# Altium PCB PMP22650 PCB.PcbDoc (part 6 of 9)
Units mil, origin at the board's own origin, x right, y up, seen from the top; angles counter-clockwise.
Board outline 11311 x 5233 mil, 8 copper layers (Layer 1, Layer 2, Layer 3, Layer 4, Layer 5, Layer 6, Layer 7, Layer 8), stack 88.6 mil thick; 633 components, 410 nets, 2503 pads, 1993 vias.
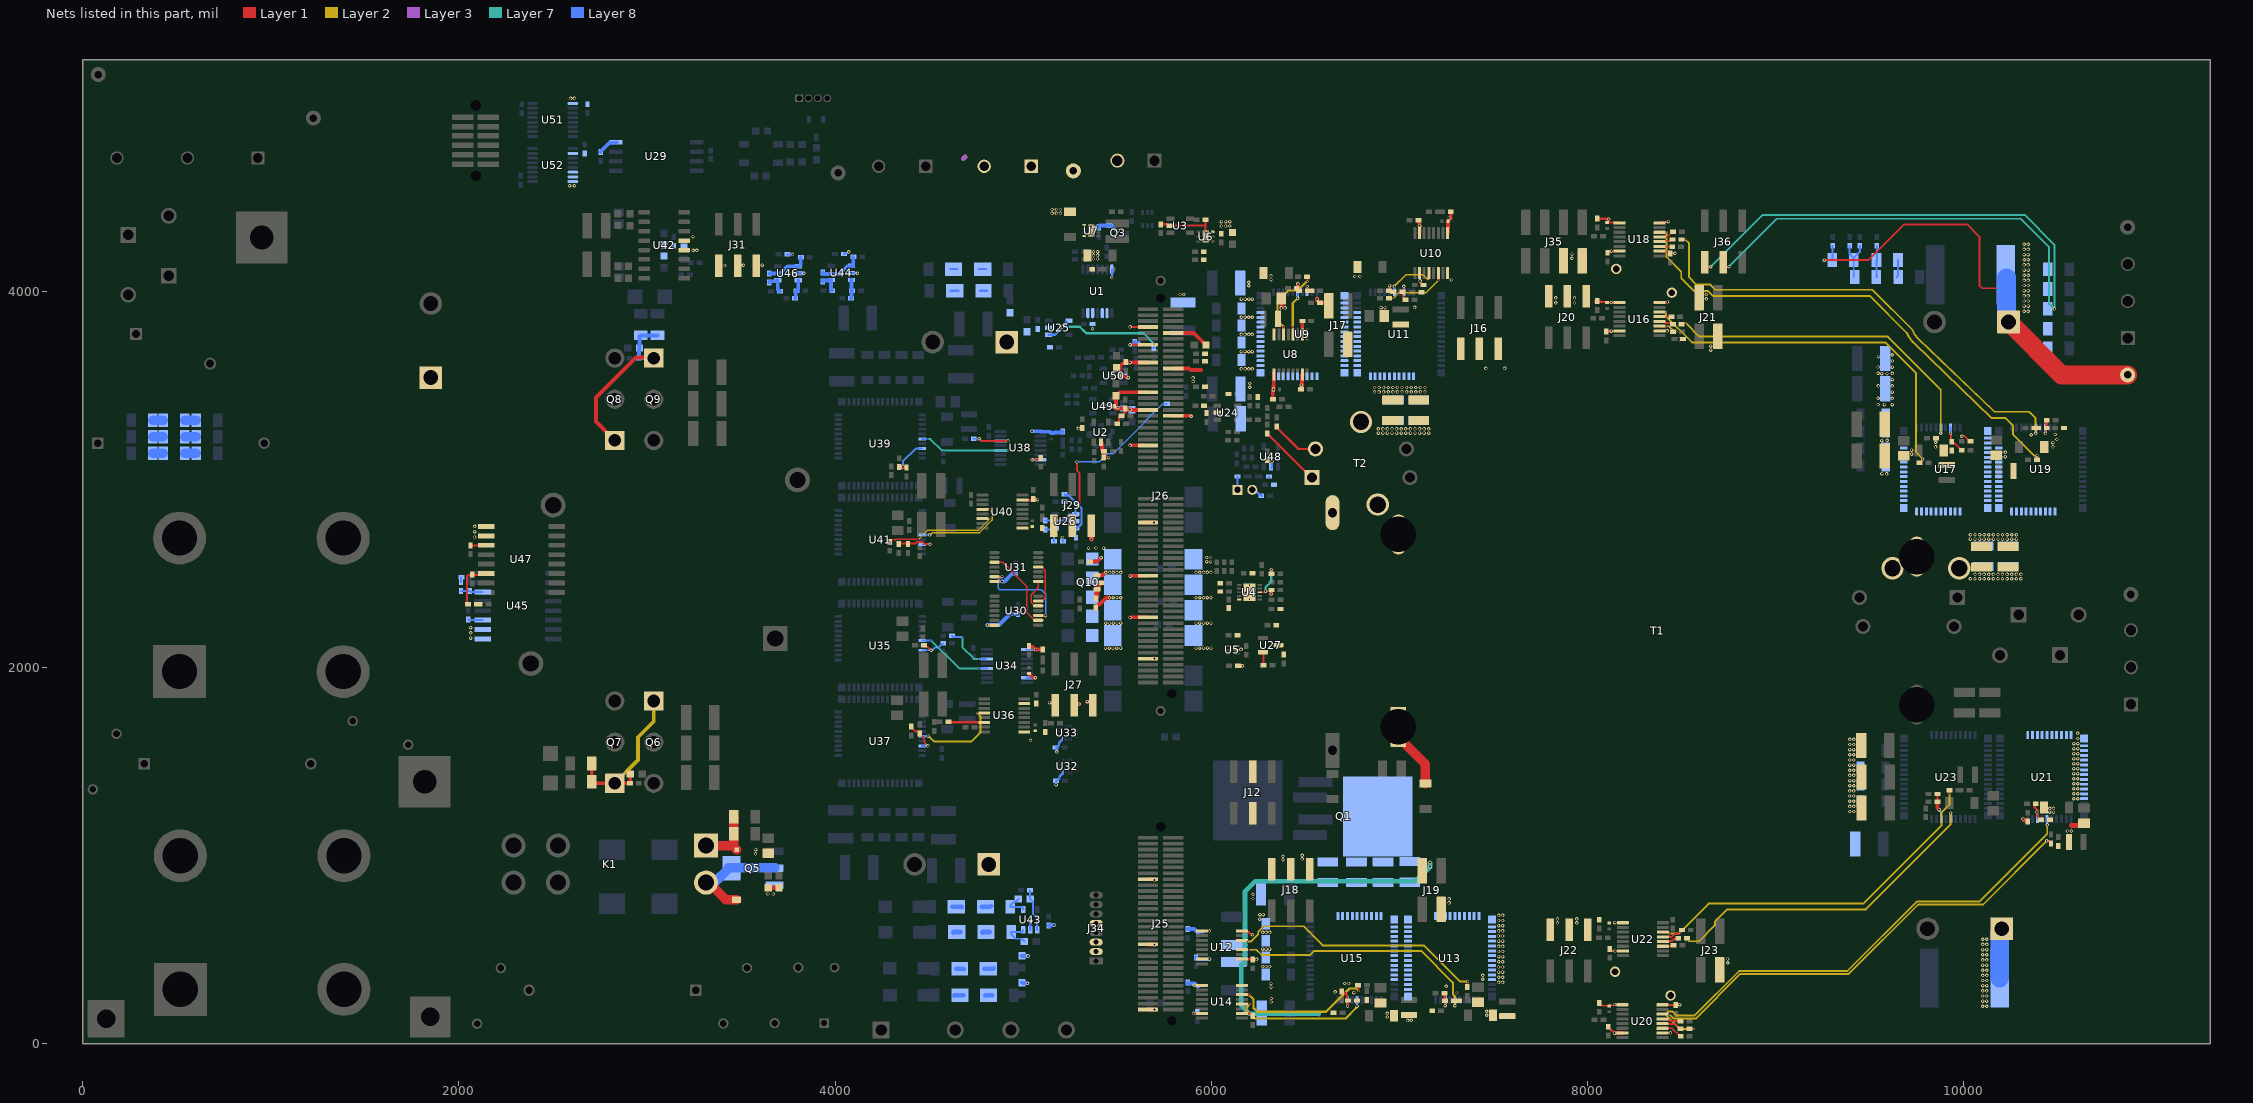
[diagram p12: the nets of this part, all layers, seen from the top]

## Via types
v1: diameter 18, hole 10, Layer 1 to Layer 8, 1759 vias
v2: diameter 8, hole 4, Layer 1 to Layer 2, 160 vias
v3: diameter 18, hole 10, Layer 1 to Layer 8, tented both sides, 34 vias
v4: diameter 8, hole 4, Layer 7 to Layer 8, 28 vias
v5: diameter 19.68, hole 7.87, Layer 1 to Layer 8, 8 vias
v6: diameter 118.11, hole 86.61, Layer 1 to Layer 8, 4 vias

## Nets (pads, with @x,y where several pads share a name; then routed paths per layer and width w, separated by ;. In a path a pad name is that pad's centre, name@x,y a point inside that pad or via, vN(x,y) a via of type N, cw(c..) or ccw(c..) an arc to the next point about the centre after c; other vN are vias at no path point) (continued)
NetR29_1: R29.1 U8.6 | length 409.5
  Layer 1 w10: R29.1@6508.62,4078 6511.62,4075 v2@6511.62,4054.62
  Layer 1 w12: U8.6@6382.27,3778.6 6383.63,3779.96 6383.63,3814.22 v2(6383.29,3814.57)
  Layer 2 w12: v2@6382,3816 6351.65,3846.35 6351.65,3948.65 6409,4006 6459.01,4006 6507.01,4054 v2@6511,4054
  other v2: 6511.62,4054
NetR34_1: R34.1 U10.6 | length 351.2
  Layer 1 w10: R34.1@6935,3963 6937,3965 R34.1@6944.62,3965 v2(6967,3965) ; U10.6@7207,4098 7207.69,4097.31 v2(7207.69,4059.9)
  Layer 2 w8: v2(6967,3965) 6968,3965 6998,3995 7142.8,3995 v2(7207.69,4059.9)
NetR39_1: R39.1 U12.6 | length 1396.3
  Layer 1 w10: U12.6@6162.57,551.05 6185.99,551.05 U12.6@6192.42,544.62 ; v1(7361,332) 7361,307 R39.1@7363,305 ; R39.1@7363,302 R39.1@7363,305 ; R39.1@7364,304 R39.1@7363,305
  Layer 2 w10: v2(6192.44,544.69) 6210.27,544.69 6249,583.42 6249,596.22 6253.82,601.05 6278.78,626 6490,626 6591.5,524.5 7130.26,524.5 7322.76,332 v1(7361,332)
NetR44_1: R44.1 U14.6 | length 777
  Layer 1 w12: U14.6@6162.57,262.05 U14.6@6164.07,260.55 ; U14.6@6163.27,262.6 6163.82,262.05 v2@6202.57,262.05 ; R44.1@6778.88,313.5 R44.1@6779.38,313 ; R44.1@6781,314 6782,313 v2(6782,283)
  Layer 2 w12: v2(6202,262) 6202,259.53 6209.03,252.5 6209.83,252.5 6224,238.33 6224,191 6244,171 6610,171 6734,295 6770,295 v2(6782,283)
NetR49_1: R49.1 U16.6 | length 2008.2
  Layer 1 w10: U16.6@8391,3891 8392,3892 v2(8418,3892) ; R49.1@9764,3089 R49.1@9765.38,3089 9769.32,3089 9776.13,3095.81 9776.13,3101.13 9780.47,3105.47 9780.47,3108.47 v1(9782,3110)
  Layer 2 w10: v2@8417,3892 8417,3868 8555.4,3729.6 9582.8,3729.6 9746.5,3565.91 9746.5,3145.5 v1(9782,3110)
NetR54_1: R54.1 U18.6 | length 2648.3
  Layer 1 w10: U18.6@8385,4315 8386,4316 v2(8420,4316) ; R54.1@10388,3106 10389,3107 v1(10389,3128)
  Layer 2 w10: v2(8420,4316) 8420,4184 8498.3,4105.7 8498.3,4071.11 8565.31,4004.1 8639.34,4004.1 8666.44,3977 9501,3977 9698.03,3779.97 9698.03,3777.87 9709.36,3758.68 ccw(c9844.57,3838.57) 9735.86,3725.23 10150,3328 10222.58,3328 10225.51,3325.07 10261,3289.58 10261,3240.42 10374.24,3127.18 v1@10389.82,3127.18
NetR59_1: R59.1 U20.6 | length 2471.6
  Layer 1 w10: U20.6@8405,160 8407,158 v2(8435,158) ; v1@10442.81,1081.61 v1(10441.28,1080.08) 10442.81,1078.55 10453.45,1078.55 10455.87,1076.13 10457.19,1076.13 10466,1067.32 R59.1@10466,1066
  Layer 2 w10: v2(8435,158) 8458,135 8575,135 8812.5,372.5 9388.31,372.5 9757.31,741.5 10102.69,741.5 v1(10441.28,1080.08)
NetR64_1: R64.1 U22.6 | length 1927.4
  Layer 1 w10: U22.6@8399,594 8401.57,591.43 8433.54,591.43 v2(8438,587) ; v2(9925,1332) 9925,1346 R64.1@9926,1347
  Layer 2 w10: v2(8438,587) 8484,587 8643.5,746.5 9466.74,746.5 9882.29,1162.05 9882.29,1231.71 9890.21,1239.63 9890.21,1240.21 9925,1275 v2(9925,1332)
NetR74_1: R74.1 U25.1 U25.4 | length 712
  Layer 7 w12: v1(5208.27,3812.6) 5300.43,3812.6 5328,3785.03 5335.03,3778 5640,3778 v4(5696,3722)
  Layer 8 w12: U25.1@5134.79,3771.2 5168.25,3771.2 5229.37,3832.31 5229.37,3840.19 5208.27,3819.09 v1(5208.27,3812.6) ; R74.1@5693,3699.62 5696,3702.62 v4@5696,3721
NetR75_1: R75.1 R76.2 | length 41.6
  Layer 8 w12: R76.2@4763.35,4119.6 R75.1@4804.98,4119.6
NetR76_1: R76.1 R77.2 | length 38.8
  Layer 8 w12: R77.2@4610.35,4119.6 R76.1@4649.18,4119.6
NetR78_2: R78.2 R83.1 U26.4 | length 121.7
  Layer 8 w12: R83.1@5116.05,2735.44 5154.82,2735.44 U26.4@5162.05,2742.67 ; R78.2@5163.43,2673.07 5163.43,2736.85 5169.24,2742.67 U26.4@5169.92,2742.67
NetR79_2: R79.2 R82.2 U26.3 | length 290.1
  Layer 8 w12: R79.2@5219.5,2922.58 5225.31,2916.76 5240.24,2916.76 5309.37,2847.63 5309.37,2764.67 5301.46,2756.76 5300.15,2756.76 5286.06,2742.67 U26.3@5278.19,2742.67 R82.2@5278.19,2696.69
NetR80_1: R80.1 R83.2 U26.1 | length 1077.9
  Layer 1 w10: v1(5278,2849) 5299.76,2870.76 5299.76,3035.49 5284.88,3050.37 v1(5284.88,3094.25)
  Layer 8 w8: v1(5284.88,3094.25) 5403.76,3094.25 5434.77,3125.26 5446.51,3137 5477.67,3137 5647.77,3307.1 5647.77,3310.88 5737.04,3400.15 5760.18,3400.15 R80.1@5763.89,3403.86
  Layer 8 w10: v1(5278,2849) 5278,2817.87 U26.1@5278.27,2817.6
  Layer 8 w12: R83.2@5116.05,2782.69 5213.69,2782.69 5244.94,2813.94 5274.66,2813.94 U26.1@5278.19,2817.47
NetR81_1: R81.1 U27.2 | length 69.7
  Layer 1 w12: U27.2@6274.4,2082.92 6277.12,2080.2 R81.1@6277.12,2014.32
NetR94_1: R94.1 R95.2 | length 35.7
  Layer 8 w12: R95.2@4770.47,4004.6 R94.1@4806.18,4004.6
NetR95_1: R95.1 R96.2 | length 41.9
  Layer 8 w12: R96.2@4614.35,4004.6 R95.1@4656.3,4004.6
NetR100_1: R100.1 U34.6 | length 265.6
  Layer 7 w10: v4(4676.65,2164.26) 4676.65,2109.22 4738.38,2047.48 v4@4763.15,2047.48
  Layer 8 w10: R100.1@4621.89,2169.7 4627.33,2164.26 v4(4676.65,2164.26) ; v4(4761.97,2047.1) 4802.77,2047.1 U34.6@4803.27,2047.6
NetR105_1: R105.1 U36.6 | length 192.3
  Layer 1 w12: R105.1@4601,1711 4601.25,1710.75 4791.45,1710.75 U36.6@4792.7,1709.5
NetR110_1: R110.1 U38.6 | length 231.5
  Layer 1 w10: v1(4765,3218) 4776.9,3206.1 v1(4918.97,3206.1)
  Layer 8 w8: U38.6@4878.27,3207.6 4879.77,3206.1 v1(4918.97,3206.1)
  Layer 8 w10: R110.1@4734.27,3216.6 4735.67,3218 v1(4765,3218)
NetR115_1: R115.1 U40.6 | length 625.3
  Layer 1 w8: R115.1@4289,2673 4297.37,2681.37 4320.79,2681.37 4322.42,2683 v2(4444,2683) ; U40.6@4778,2792 v2(4820,2792)
  Layer 2 w8: v2@4442.67,2682.67 4490.6,2730.6 4519.52,2730.6 4521.42,2732.5 4762.5,2732.5 4821,2791 v2@4821,2792
NetR125_2: R125.2 R129.2 U43.3 | length 167.3
  Layer 8 w10: U43.3@4999.22,606.46 4999.22,601.61 4992.4,594.8 R129.2@4935.71,594.8 4935.71,583.98 4960.39,559.3 4991.42,559.3 R125.2@5005.12,545.6
NetR126_2: R126.2 R131.2 U44.3 | length 100.5
  Layer 8 w20: R126.2@4084.82,3964.55 4085.19,3964.55 4087.01,3966.36 4087.01,4003.14 R131.2@4088.82,4004.95 ; U44.3@4086.62,4061.63 4086.62,4006.76 4088.43,4004.95 R131.2@4088.82,4004.95 ; R131.2@4089.19,4004.95 R131.2@4088.82,4004.95
NetR127_2: R127.2 R128.1 | length 40.2
  Layer 8 w25: R127.2@4628.27,592.6 4630.47,594.8 R128.1@4667.54,594.8
NetR128_2: R128.2 R129.1 | length 39.2
  Layer 8 w25: R128.2@4783.27,592.6 4785.47,594.8 R129.1@4821.54,594.8
NetR130_1: R130.1 R139.2 U43.1 | length 226.7
  Layer 8 w10: R130.1@5035.24,816.6 5035.24,772.47 R139.2@5037.11,770.6 5038.01,770.6 5051.71,756.9 5051.71,691.87 5074.02,669.56 U43.1@5074.02,606.46
NetR132_2: R132.2 R138.1 U45.14 | length 117.5
  Layer 8 w10: R132.2@2010.65,2408.25 R138.1@2057.89,2408.25 2062.54,2403.6 U45.14@2126.26,2403.6
NetR133_1: R133.1 R140.2 U44.1 | length 232.7
  Layer 8 w20: R140.2@3933.69,4101.17 3933.69,4097.23 3935.51,4095.42 3939.44,4095.42 3940.99,4093.87 4023.14,4093.87 4063.89,4134.62 4084.8,4134.62 U44.1@4086.62,4136.43 4094.49,4136.43 4096.57,4138.51 R133.1@4096.57,4184.55
NetR134_2: R134.2 R135.1 | length 50.1
  Layer 8 w25: R134.2@4623.71,728.8 R135.1@4664.54,728.8 4672.06,728.8 R135.1@4673.27,727.6
NetR135_2: R135.2 R136.1 | length 51.1
  Layer 8 w25: R135.2@4778.71,728.8 R136.1@4817.54,728.8 4824.47,728.8 R136.1@4828.27,732.6
NetR136_2: R136.2 R139.1 U43.4 | length 141.7
  Layer 8 w10: R139.1@4974.12,770.6 4960.42,756.9 4952.3,756.9 4931.71,736.31 R136.2@4931.71,728.8 4992.4,728.8 4999.22,721.99 U43.4@4999.22,714.73
NetR137_2: R137.2 R140.1 U44.4 | length 111.6
  Layer 8 w20: R140.1@3933.69,4053.93 3933.69,4057.86 3935.51,4059.67 3968.52,4059.67 3970.47,4061.63 U44.4@3978.35,4061.63 3978.35,4006.98 3980.38,4004.95 R137.2@3984.32,4004.95
NetR142_1: R142.1 R143.2 | length 50.1
  Layer 8 w25: R142.1@4633.27,257.6 4635.27,259.6 R142.1@4643.7,259.6 R143.2@4682.53,259.6
NetR143_1: R143.1 R144.2 | length 38.1
  Layer 8 w25: R143.1@4798.27,257.6 4799.77,259.1 4835.03,259.1 R144.2@4835.53,258.6
NetR145_1: R145.1 R146.2 U46.3 | length 104.9
  Layer 8 w20: R145.1@3787.51,3965.57 3788.77,3965.57 3790.58,3967.38 3790.58,4001.75 3792.39,4003.57 R146.2@3793.65,4003.57 3797.58,4003.57 3803.31,4009.29 U46.3@3803.31,4060.16
NetR148_1: R148.1 R154.2 U46.1 | length 226.5
  Layer 8 w20: R154.2@3649.89,4096.19 3708.5,4096.19 3747.28,4134.97 U46.1@3803.31,4134.97 3811.18,4134.97 3817.27,4141.05 R148.1@3817.27,4181.57
NetR149_2: R149.2 R155.1 U47.14 | length 242.5
  Layer 1 w10: R149.2@2047,2338 2043,2342 2043,2487.61 2048.86,2493.47 2123.13,2493.47 U47.14@2129.26,2499.6
NetR150_1: R150.1 R151.2 | length 40.8
  Layer 8 w25: R150.1@4643.7,400.6 R151.2@4679.53,400.6 4680.27,400.6 R151.2@4683.27,397.6
NetR151_1: R151.1 R152.2 | length 50.4
  Layer 8 w25: R151.1@4793.7,400.6 R152.2@4835.53,400.6 4841.27,400.6 R152.2@4843.27,402.6
NetR153_2: R153.2 R154.1 U46.4 | length 116.8
  Layer 8 w20: R154.1@3649.89,4048.94 3649.89,4052.88 3651.7,4054.69 3681.7,4054.69 3687.17,4060.16 U46.4@3695.04,4060.16 3695.04,4010.1 3702.57,4002.57 R153.2@3706.51,4002.57
NetR161_2: R161.2 R167.1 | length 61.5
  Layer 8 w50: R167.1@541.49,3315.6 R161.2@603.02,3315.6
NetR162_2: R162.2 R168.1 | length 61.5
  Layer 8 w50: R168.1@541.49,3228.58 R162.2@603.02,3228.58
NetR163_2: R163.2 R169.1 | length 61.5
  Layer 8 w50: R169.1@541.49,3141.15 R163.2@603.02,3141.15
NetR167_2: R167.2 R173.1 | length 56
  Layer 8 w50: R173.1@371.35,3315.6 R167.2@427.31,3315.6
NetR168_2: R168.2 R174.1 | length 56
  Layer 8 w50: R174.1@371.35,3228.58 R168.2@427.31,3228.58
NetR169_2: R169.2 R175.1 | length 56
  Layer 8 w50: R175.1@371.35,3141.15 R169.2@427.31,3141.15
NetR192_1: R192.1 R193.1 R206.1 R207.1 | length 259.7
  Layer 8 w10: R206.1@9393.27,4243.98 9393.27,4200.51 9413.27,4180.51 R192.1@9413.27,4167.6 ; R192.1@9415.35,4167.6 9415.35,4080.51 R193.1@9418.27,4077.6 ; R192.1@9418.27,4172.6 9418.27,4181.34 9448.27,4211.34 R207.1@9448.27,4243.98
NetR193_2: R193.2 R197.1 R208.1 | length 177.2
  Layer 8 w10: R197.1@9536.18,4167.6 9536.18,4079.69 R193.2@9538.27,4077.6 ; R197.1@9538.27,4157.6 R208.1@9538.27,4243.98
NetR197_2: R197.2 R201.1 | length 92.9
  Layer 8 w10: R201.1@9643.27,4077.6 9650.35,4084.69 R197.2@9650.35,4167.6
NetR204_1: R204.1 U4.8 | length 185.7
  Layer 1 w10: U4.8@6257.87,2401.6 6257.94,2401.68 6282.35,2401.68 v1(6288.27,2407.6)
  Layer 1 w12: R204.1@6318.27,2497.6 6318.75,2498.08 6318.75,2522.12 v1(6318.27,2522.6)
  Layer 7 w12: v1(6288.27,2407.6) 6288.27,2427.6 6318.27,2457.6 v1(6318.27,2522.6)
NetR209_1: R209.1 U16.3 | length 124
  Layer 1 w12: U16.3@8381,3817 8382,3816 v2(8418,3816) ; R209.1@8454.38,3787 8455.38,3788 v2@8473,3788
  Layer 2 w10: v2(8418,3816) 8432,3816 8460,3788 v2(8474,3788)
NetR210_1: R210.1 U16.4 | length 81.4
  Layer 1 w10: U16.4@8378,3845 U16.4@8385,3845 ; U16.4@8407.08,3845 8419.58,3832.5 8446.88,3832.5 R210.1@8453.38,3826
  Layer 1 w12: U16.4@8385,3841 U16.4@8405.22,3841
NetR211_1: R211.1 U16.5 | length 58.6
  Layer 1 w10: U16.5@8390,3864 8392.25,3866.25 8445.13,3866.25 R211.1@8445.38,3866
  Layer 1 w12: U16.5@8390,3867 U16.5@8391.57,3868.57
NetR212_1: R212.1 U18.3 | length 66
  Layer 1 w8: U18.3@8385,4239 8385.25,4239.25 8449.13,4239.25 R212.1@8450.38,4238
NetR213_1: R213.1 U18.4 | length 68.3
  Layer 1 w8: U18.4@8388,4265 8392.57,4269.57 8443.95,4269.57 R213.1@8451.38,4277
NetR214_1: R214.1 U18.5 | length 81
  Layer 1 w8: U18.5@8386,4290 8423.38,4290 8431.69,4298.31 8431.75,4298.31 8451.44,4318 R214.1@8455.38,4318
NetR215_1: R215.1 U20.4 | length 109.4
  Layer 1 w10: U20.4@8398.3,108.5 8401.37,105.43 8436.7,105.43 ; 8435,106 8465.44,106 8490.44,81 R215.1@8494.38,81
NetR216_1: R216.1 U20.5 | length 98.9
  Layer 1 w10: U20.5@8398.3,133.5 8401.37,130.43 8433.62,130.43 ; 8435,128 8441.5,121.5 8493.88,121.5 R216.1@8494.38,121
NetR217_1: R217.1 U20.3 | length 116.7
  Layer 1 w10: U20.3@8398.3,83.5 8448.94,83.5 8492.44,40 R217.1@8497,40
NetR218_1: R218.1 U22.4 | length 89.9
  Layer 1 w12: U22.4@8405,545 U22.4@8405.5,545.5 ; U22.4@8405,546 U22.4@8405.5,545.5 ; U22.4@8408.57,542.43 U22.4@8405.5,545.5 ; R218.1@8482.38,563 8476.57,557.19 8457.82,557.19 8447.94,547.31 8436.87,547.31 8436.13,546.57 8406.57,546.57 U22.4@8405.5,545.5
NetR219_1: R219.1 U22.5 | length 118.7
  Layer 1 w10: U22.5@8400.3,569.5 8446.8,569.5 8454.54,577.24 8454.54,577.57 8462.28,585.31 8480.69,585.31 8490.63,595.25 8490.63,599.19 8497.44,606 R219.1@8501.38,606
NetR220_1: R220.1 U22.3 | length 56
  Layer 1 w10: U22.3@8403,520 8404.75,521.75 8455.13,521.75 R220.1@8457.38,524
NetU30_9: U30.9 U31.3 | length 441.8
  Layer 1 w8: U31.3@4847.13,2561.17 4890.83,2561.17 5019.05,2432.95 5019.05,2293.68 5060.34,2252.39 U30.9@5079.41,2252.39
NetU30_10: U30.10 U31.6 | length 522.7
  Layer 1 w8: U31.6@4847.13,2484.39 4886.47,2484.39 v1@4888.27,2482.6 ; U30.10@5088.27,2277.6 5088.46,2277.79 5118.07,2277.79 v1(5118.27,2277.6)
  Layer 8 w8: v1@4888.09,2482.77 4883.52,2482.77 4867.63,2466.88 4867.63,2421.69 4873.21,2416.1 5095.93,2416.1 5106.77,2405.26 5106.77,2403.85 5118.27,2392.35 v1(5118.27,2277.6)
  other v1: 4887.13,2484.39
NetU30_12: U30.12 U31.8 | length 171.5
  Layer 1 w8: U30.12@5079.41,2329.17 5060.34,2329.17 5042.35,2347.15 5042.35,2387.95 5079.41,2425.01 U31.8@5079.41,2458.8
NetU30_13: U30.13 U31.11 | length 233.9
  Layer 1 w8: U30.13@5079.41,2354.76 5098.48,2354.76 5116.47,2372.74 5116.47,2517.59 5098.48,2535.57 U31.11@5079.41,2535.57
OC_H_A: U10.4 U11.48 | length 292.4
  Layer 1 w10: v2(7155.69,4059.9) 7155.69,4096.69 U10.4@7156,4097
  Layer 2 w8: v1@6972.84,4028 7033.84,4089 7126.59,4089 v2(7155.69,4059.9)
  Layer 8 w8: U11.48@6972.97,3993.03 6972.97,3996.74 v1(6973,4028)
OC_H_B: U14.4 U15.48 | length 753
  Layer 1 w12: U14.4@6163.82,212.05 v2@6202.57,212.05
  Layer 2 w12: v2(6204,212) 6186.5,194.5 6186.5,179 6229.5,136 6713.99,136 6770.5,192.51 6770.5,194.88 v1@6776.62,201
  Layer 8 w12: U15.48@6773.27,239.6 U15.48@6774.85,241.18 ; v1(6775,201) 6774.93,201.07 6774.93,234.93 U15.48@6776,236
OC_H_C: R213.2 U19.48 | length 2502.6
  Layer 1 w10: R213.2@8496,4279 8498,4277 R213.2@8498.62,4277 v2(8520,4277)
  Layer 2 w10: v2(8520,4277) 8539.5,4257.5 8539.5,4076.57 8578.98,4037.1 8653.01,4037.1 8680.11,4010 9514.67,4010 9727.72,3796.95 ccw(c9844.57,3838.57) 9758.75,3749.01 10163.67,3361 10347,3361 10349.93,3358.07 10382,3326 10382,3249 v1@10384,3247
  Layer 8 w10: U19.48@10382.54,3278.46 10383.04,3277.96 v1(10383,3246) v1@10384,3245 ; U19.48@10383.04,3277.98 U19.48@10383.09,3278.02
OC_H_D: R218.2 U23.48 | length 1790.2
  Layer 1 w10: v2(8530,546) R218.2@8530,563
  Layer 2 w10: v2(8530,546) 8592.93,546 8677.27,630.34 8677.27,649.34 8743.42,715.5 9479.58,715.5 9929.47,1165.39 9929.47,1225.47 v3@9930,1226
  Layer 8 w10: v3(9931,1228) 9931.51,1227.49 9931.51,1196.49 U23.48@9932,1196 ; U23.48@9932.02,1183.06 U23.48@9932.02,1195.86
OC_H_PFC_1: U36.4 U37.48 | length 488.1
  Layer 1 w10: v2(4756.52,1759.53) 4794.47,1759.53 U36.4@4796,1758
  Layer 2 w10: v1@4498,1636 4525,1609 4725.08,1609 4773,1656.92 4773,1743.04 v2(4756.52,1759.53)
  Layer 8 w10: U37.48@4462,1637 4462.57,1636.43 4493.73,1636.43 v1(4494.12,1636.82)
OC_H_PFC_2: U40.4 U41.48 | length 494.9
  Layer 1 w8: U40.4@4786,2843 4787,2842 v2(4820,2842)
  Layer 2 w8: v1@4505,2708 4506.71,2708 4515.8,2717.1 4525.11,2717.1 4527.02,2719 4768.09,2719 4834.5,2785.41 4834.5,2827.5 v2(4820,2842)
  Layer 7 w8: v1@4510.27,2708.39 v1@4510.65,2708
  Layer 8 w8: U41.48@4460,2709 4461.81,2707.19 4494.81,2707.19 v1@4495,2707
  other v1: 4503,2707
OC_L_A: U8.4 U9.48 | length 233.6
  Layer 1 w12: U8.4@6432.27,3773.6 U8.4@6433.63,3774.96 ; U8.4@6433.98,3778.02 v2@6433.98,3814.57
  Layer 2 w12: v2@6433,3814 6433,3939 v1(6459,3965)
  Layer 8 w12: v1(6459,3965) 6458.65,3965.35 6458.65,3997.65 U9.48@6459,3998
  other v2: 6433.29,3814.57
OC_L_B: U12.4 U13.48 | length 1371.9
  Layer 1 w10: U12.4@6162.57,501.05 v2(6201,501)
  Layer 2 w10: v2(6201,501) 6239.5,501 6266.56,473.94 6524.94,473.94 6544.5,493.5 7117.42,493.5 7284.5,326.42 7284.5,299.95 7284.5,264.92 7295,254.42 v1(7295,203)
  Layer 8 w10: U13.48@7293.27,234.88 U13.48@7294.85,233.3 ; v1(7295,203) 7294.93,203.07 7294.93,232.93 U13.48@7296,234
OC_L_C: R210.2 U17.48 | length 1792.2
  Layer 1 w10: R210.2@8498,3826 8499,3825 8507,3833 v2(8522,3833)
  Layer 2 w10: v2@8522.16,3833.16 8594.73,3760.6 9596.48,3760.6 9878,3479.08 9878,3249 v1@9877,3248
  Layer 8 w10: U17.48@9877,3277 9878.04,3275.96 v1(9878,3247) v1(9878,3247)
OC_L_D: R215.2 U21.48 | length 2746.8
  Layer 1 w10: R215.2@8537,82 8539,80 v2(8564,80)
  Layer 2 w10: v2@8563.85,80 8491.08,80 8419.5,151.58 8419.5,164.42 8428.58,173.5 8451.5,173.5 8474.5,150.5 8568.58,150.5 8806.08,388 9381.89,388 9750.89,757 10083,757 10444,1118 v1(10444,1165)
  Layer 8 w10: U21.48@10442,1198 10443.43,1196.57 10443.43,1165.57 v1(10444,1165)
  Layer 8 w12: U21.48@10442.87,1183.06 U21.48@10442.87,1195.86
OC_L_PFC_1: U34.4 U35.48 | length 404.4
  Layer 7 w10: v4@4511.98,2144.47 4659.36,1997.1 v4(4761.97,1997.1)
  Layer 8 w10: U35.48@4463.12,2144.47 v4(4510,2144.47) ; v4(4761.97,1997.1) U34.4@4806.97,1997.1 4807.77,1997.1 U34.4@4808.27,1997.6
OC_L_PFC_2: U38.4 U39.48 | length 528.1
  Layer 7 w10: v4@4493,3216 4506,3216 4565.9,3156.1 v4(4918.97,3156.1)
  Layer 8 w10: U39.48@4461.27,3216.6 4461.63,3216.96 U39.48@4463.12,3216.96 v4(4492.12,3216.96) ; U38.4@4873.27,3157.6 4874.77,3156.1 U38.4@4878.97,3156.1 v4(4918.97,3156.1)
PFC_4H_G: C197.1 Q8.1 Q9.1 R121.2 R122.2 R124.2 | length 960.9
  Layer 1 w20: Q8.1@2828.43,3208.7 2728.27,3308.86 2728.27,3436.6 2941.27,3649.6 Q9.1@3034.27,3649.6
  Layer 8 w20: C197.1@2954.89,3644.6 C197.1@2955.52,3644.6 ; Q9.1@3035.21,3646.5 2960.72,3646.5 2958.83,3644.6 C197.1@2955.52,3644.6 ; R121.2@3055.26,3767.3 R124.2@2966.26,3767.3 2959.76,3760.8 R122.2@2959.76,3699.6 2957.33,3697.16 2957.33,3646.41 C197.1@2955.52,3644.6
PFC_4L_G: C196.1 Q6.1 Q7.1 R117.2 R118.2 R119.2 | length 888.7
  Layer 1 w20: R119.2@2705.36,1491.6 R117.2@2705.35,1393.6 2713.25,1385.7 Q7.1@2828.43,1385.7 2828.53,1385.6 C196.1@2908.65,1385.6 2908.96,1385.6 2910.77,1387.41 R118.2@2910.77,1435.6
  Layer 2 w20: Q7.1@2819.27,1384.6 2827.32,1384.6 Q7.1@2828.43,1385.7 2952.41,1509.68 2952.41,1630.95 3035.21,1713.75 Q6.1@3035.21,1823.5
PGND: C1.2 C22.2 C23.2 C24.1 C25.1 C26.1 C27.2 C28.2 C29.2 C30.2 C31.2 C32.2 C33.1 C34.1 C35.1 C36.2 C37.2 C38.1 C39.2 C40.2 C41.1 C42.1 C43.2 C44.2 C45.2 C46.2 C47.1 C48.1 C49.2 C50.2 C51.1 C52.1 C54.2 C56.1 C60.1 C61.2 C62.2 C63.1 C64.1 C65.2 C66.2 C67.2 C68.2 C69.1 C70.1 C71.2 C72.2 C73.1 C74.1 C76.2 C78.1 C83.2 C85.1 C98.2 C100.1 C105.2 C107.1 C120.2 C122.1 C126.2 C127.2 C129.2 C131.2 C132.2 C133.2 C134.2 C135.2 C136.2 C137.2 C139.2 C141.2 C142.2 C143.2 C144.1 C145.1 C147.2 C149.1 C162.2 C164.1 C169.2 C171.1 C184.2 C186.1 C193.2 C194.2 C195.2 C198.2 C202.2 C203.2 C204.2 C205.2 C206.2 C207.2 C208.1 C209.2 C210.2 C211.2 C212.2 C213.2 C214.2 C215.1 C223.1 C224.1 C225.1 C232.2 C233.2 C236.2 C237.2 C239.2 C241.2 C242.1 C244.2 C246.2 C249.2 C251.2 C253.2 C255.2 J2.1 J2.2 J3.1 J3.2 J4.1 J4.2 J5.1 J5.2 J12.3 J12.4 J15.2 J16.2 J16.4 J16.6 J17.4 J18.2 J18.4 J18.6 J19.4 J20.2 J20.4 J20.6 J22.2 J22.4 J22.6 J25.135 J25.157 J25.179 J26.7 J26.10 J26.13 J26.19 J26.22 J26.29 J26.35 J26.38 J26.47 J26.65 J26.83 J26.97 J26.111 J27.2 J27.4 J27.6 J29.2 J29.4 J29.6 J31.2 J31.4 J31.6 J34.2 J34.3 J34.5 J35.1 J35.3 J37.1 J37.2 L3.1 L5.1 Q3.2 Q5.3 Q10.2 R6.1 R10.1 R11.1 R12.1 R18.1 R21.1 R26.1 R28.1 R33.1 R36.1 R38.1 R43.1 R48.1 R53.1 R58.1 R63.1 R66.1 R73.2 R78.1 R91.2 R99.1 R104.1 R109.1 R114.1 R132.1 R141.2 R147.2 R149.1 R156.1 R159.2 R164.2 R166.2 R171.2 R172.2 R178.1 R185.1 TP5.1 U1.7 U1.9 U1.10 U1.12 U1.13 U2.2 U3.2 U4.5 U4.11 U5.5 U6.3 U6.7 U7.1 U7.4 U7.9@5360.87,4324.44 U8.2 U8.8 U8.9 U8.15 U9.17 U9.18 U9.19 U9.20 U9.21 U9.22 U9.23 U9.24 U9.25 U9.26 U9.27 U9.28 U9.29 U9.30 U9.31 U9.32 U9.33 U9.34 U9.35 U9.36 U9.37 U9.38 U9.39 U10.9 U10.15 U12.2 U12.8 U12.9 U12.15 U13.17 U13.18 U13.19 U13.20 U13.21 U13.22 U13.23 U13.24 U13.25 U13.26 U13.27 U13.28 U13.29 U13.30 U13.31 U13.32 U13.33 U13.34 U13.35 U13.36 U13.37 U13.38 U13.39 U14.9 U14.15 U16.9 U16.15 U18.9 U18.15 U20.9 U20.15 U22.9 U22.15 U24.2 U25.2 U26.2 U27.3 U29.4 U30.7 U31.7 U32.12 U33.12 U34.9 U34.15 U36.9 U36.15 U38.9 U38.15 U40.9 U40.15 U42.4 U42.5 U43.2 U44.2 U45.9 U45.10 U45.11 U46.2 U47.9 U47.10 U47.11 U48.2 U49.2 U50.2 U51.9 U52.2 U52.6 U52.7 U52.8 | length 7117.3
  Layer 1 w10: C211.2@2061.27,2651.22 2062.89,2649.6 U47.11@2129.26,2649.6 ; C239.2@6293,3106 6302,3097 v1(6323,3097) ; R58.1@8063,218.62 8063,214.68 8069.81,207.87 8073.75,207.87 8078.62,203 8114,203 8116.62,205.62 8137.46,205.62 8141.84,210 v1@8143,210 ; C105.2@8110,83.68 C105.2@8110,86 ; C120.2@8116,508 8116,503.68 8124.81,494.87 8144.13,494.87 v1@8144.75,494.25 ; v1@8142.47,59.53 v1(8144,58) ; v1(8144,210) v1@8143,210 ; v1(8145,494) v1@8144.75,494.25 ; U20.9@8185.7,208.5 8184.95,209.25 8143.75,209.25 v1@8143,210 ; U22.15@8187.7,494.5 8187.45,494.25 v1@8144.75,494.25
  Layer 1 w12: v1(4808.27,2227.6) 4808.67,2227.2 4846.73,2227.2 U30.7@4847.13,2226.8 ; U31.7@4847.13,2458.8 v1(4887.13,2458.8) v1@4888.27,2457.6 ; U40.15@4995.3,2892.5 4996.86,2890.94 5052.06,2890.94 C184.2@5053,2890 ; v1(5038.57,1614.1) v1@5039.33,1614.86 ; v1@5051.57,3106.1 5052.33,3106.86 5087.46,3106.86 5093.27,3112.67 C169.2@5093.27,3116.22 C169.2@5093.27,3117.6 ; C184.2@5053,2895 5053.48,2895.48 5073.59,2895.48 v1(5074.73,2894.33) ; v1(5293.27,3272.6) C26.1@5313.27,3272.6 ; C23.2@5428.27,3117.6 5428.61,3117.94 5452.92,3117.94 v1(5453.27,3117.6) ; C202.2@5508.81,3300.91 5508.81,3329.26 5519.02,3339.46 C127.2@5522.95,3339.46 5526.89,3339.46 5532.7,3345.28 5532.7,3349.21 5539.14,3355.65 C241.2@5539.14,3378.83 ; v1(5568.27,3717.6) 5568.36,3717.51 5663.32,3717.51 J26.13@5663.41,3717.42 ; v1(5568.27,3812.6) 5568.61,3812.25 5663.06,3812.25 J26.7@5663.41,3811.91 ; C25.1@5730.34,4357.91 5766.56,4357.91 5773.5,4350.97 U3.2@5783.34,4350.97 5968.27,4350.97 5968.27,4314.56 5969.45,4313.38 U6.7@5969.45,4292.91 ; v1@5905,162.05 U14.15@5948.82,162.05 ; v1(5909,312) 5949.92,312 U14.9@5949.97,312.05 5948.82,312.05 U14.9@5948.27,312.6 ; U12.15@5943.27,452.6 5988.27,452.6 5989.82,451.05 v1(5989.97,451.05) ; U14.15@5948.27,162.6 U14.15@5948.82,162.05 ; U14.15@5949.97,162.05 U14.15@5948.82,162.05 ; U12.9@5953.27,602.6 5954.82,601.05 v1(5989.97,601.05) ; C24.1@5967.89,4382.55 5968.67,4381.77 5968.67,4350.97 ; U5.5@6135.45,2095.29 6136.53,2096.37 6155.96,2096.37 6157.19,2097.6 v1(6158.27,2097.6) ; U12.2@6152.57,451.05 U12.2@6153.26,450.36 ; U12.2@6162.57,451.05 6163.61,450 v1(6241,450) ; U12.8@6162.57,601.05 6168,595.62 6197.69,595.62 6212.31,581 v1(6219,581) ; R48.1@8041,3946 8073.81,3946 8075.19,3944.62 8096.13,3944.62 C85.1@8098,3942.75 ; R53.1@8063,4388.62 8064.47,4387.15 v1@8113,4387.15 ; C85.1@8098,3943 8098.63,3942.37 8125.63,3942.37 v1(8126,3942) ; C83.2@8099,3787.62 8100.38,3789 v1@8129,3789 ; C100.1@8101,4367.75 C100.1@8104,4367.75 C100.1@8105.97,4367.75 ; C98.2@8103,4205.04 8111.81,4213.85 8125.85,4213.85 v1(8127,4215) ; C105.2@8113,90 8113,85.68 8122.57,76.12 8124.26,76.12 8142.38,58 v1(8144,58) ; v1(8113,4386) 8107.84,4380.84 8107.84,4369.62 C100.1@8105.97,4367.75 ; v1(8126,3790) 8126.75,3790.75 8162.75,3790.75 U16.15@8164,3792 ; v1@8127,4216 8127.75,4215.25 8169.45,4215.25 U18.15@8169.7,4215.5 ; v1@8128,3943 8128,3942.52 8128.77,3941.75 8169.45,3941.75 U16.9@8169.7,3941.5 ; U18.9@8167,4366 8165.43,4367.57 8137.68,4367.57 8137.51,4367.75 C100.1@8105.97,4367.75
  Layer 1 w20: C149.1@5030.57,1969.39 5052.85,1947.1 v1(5064.57,1947.1) ; C147.2@5030.57,2116.91 5030.57,2112.98 5032.38,2111.17 5050.5,2111.17 v1(5064.57,2097.1) 5102.49,2097.1 R99.1@5103.27,2096.32 ; J27.2@5167.78,1780.59 J27.2@5167.78,1807.51 ; J27.4@5273.27,1807.6 5273.36,1807.51 v1(5297.78,1807.51) ; v1(5340,1820) 5380.85,1820 5368.36,1807.51 J27.6@5368.27,1807.6 ; C233.2@5355.03,2564.84 5392.84,2564.84 v1@5413,2585 ; R21.1@5366.76,4119.16 5370.7,4119.16 R21.1@5372.51,4120.97 ; C232.2@5386.3,2320.79 5386.3,2324.73 5398.36,2336.78 5404.53,2336.78 5441.81,2374.06 5456.81,2374.06 v1(5458.27,2372.6) ; Q10.2@5393.65,2490.05 Q10.2@5391.84,2491.86 5393.65,2493.67 5424.34,2493.67 v1(5438.27,2507.6) ; U2.2@5417.35,3195.21 5419.16,3193.4 5419.16,3157.14 5425.21,3151.1 5428.77,3151.1 5428.77,3118.48 C23.2@5428.58,3118.29 ; C244.2@5481.73,3390.6 5493.49,3378.83 C241.2@5539.14,3378.83 ; C244.2@5483.27,3392.6 5493.27,3402.6 C141.2@5493.27,3446.1 ; C141.2@5502.95,3455.79 5512.61,3465.45 J26.29@5663.41,3465.45 ; C249.2@5511.13,3552.31 5512.94,3550.5 5524.26,3550.5 5527.04,3547.73 5553.14,3547.73 v1(5558.27,3542.6) ; C249.2@5514.13,3552.31 5513.64,3552.31 5511.83,3554.12 5511.83,3596.2 5509.54,3598.5 5509.54,3599.48 5528.81,3618.76 5556.13,3618.76 5557.94,3620.57 5557.94,3624.5 5588.37,3624.5 5589.95,3622.93 J26.19@5663.41,3622.93 ; C241.2@5543.27,3378.98 5543.27,3375.04 5545.08,3373.23 5556.16,3373.23 5556.79,3372.6 v1(5568.27,3372.6) 5569.91,3370.96 J26.35@5663.41,3370.96 ; v1(5568.27,2267.6) 5569.27,2268.6 J26.97@5663.41,2268.6 ; v1(5568.27,2487.6) 5569.74,2489.07 J26.83@5663.41,2489.07 ; v1(5568.27,3182.6) J26.47@5643.27,3182.6 ; J26.65@5628.27,2772.6 5628.67,2773 v1(5696,2773) ; J25.179@5663.41,183.05 5663.57,182.89 5697.97,182.89 v1(5698.27,182.6) ; J25.157@5663.41,529.51 5663.57,529.35 5696.52,529.35 v1(5698.27,527.6) ; J25.135@5663.41,875.96 5663.57,875.81 5695.06,875.81 v1(5698.27,872.6) ; J26.111@5677.03,2048.28 5696.28,2048.28 v1(5697,2049) ; J26.38@5797.27,3339.46 5891.4,3339.46 v1(5893.27,3337.6) ; J26.22@5797.27,3591.43 5881.15,3591.43 5889.99,3582.6 5945,3582.6 ; J26.10@5797.27,3780.41 5797.43,3780.25 5906.26,3780.25 5968,3718.51 C210.2@5968,3710 ; C30.2@6140.62,2012 6141.62,2011 v1(6165,2011) ; v1(6318.27,2392.6) 6318.27,2412.5 R18.1@6319.23,2413.46 ; R28.1@6326.32,3428.6 6326.32,3475.98 v1(6330.09,3479.75) 6330.09,3496.29 6332.05,3498.24 6332.05,3557.81 U8.9@6333.98,3559.74 ; v1(6372.15,3913.6) 6372.15,3958.48 C38.1@6372.27,3958.6 ; v1@6389.5,3916.37 v1(6392.27,3913.6) ; R26.1@6459,4014 6460,4015 v1(6460,4041) ; C39.2@6482.55,3480 6482.55,3558.31 U8.15@6483.98,3559.74 ; U8.2@6483.48,3793.84 6483.48,3843.43 C40.2@6483.65,3843.6 ; v1@6562,3965 v1(6562,3961) 6562,3952.69 6572.69,3942 C43.2@6578,3942 ; C43.2@6577.62,3941 6614,3941 J17.4@6627,3928 ; C54.2@7100.89,4378.6 7103.45,4378.6 7105.26,4376.79 7105.26,4350.9 7107.77,4348.39 7107.77,4311.97 U10.15@7106.69,4310.9 ; U10.9@7256.69,4310.9 7258.62,4312.83 7258.62,4372.39 7258.94,4372.71 7258.94,4373.6 7272.89,4387.55 R33.1@7272.89,4425.6 ; v1@8146.38,58.62 8146.5,58.5 U20.15@8185.7,58.5
  Layer 1 w25: C213.2@3644.27,831.1 R156.1@3700.27,831.1 ; v1(5363,2683) 5363,2772.33 J29.6@5368.27,2777.6
  Layer 3 w25: 4681.33,4706.51 4690.42,4715.6
  Layer 8 w10: R132.1@2010.65,2455.49 2010.65,2478.93 C215.1@2012.61,2480.9 ; C204.2@2049.27,2256.98 2052.65,2253.6 U45.11@2126.26,2253.6 ; v1@5906,163 5919.38,163 C76.2@5926,169.62 ; U48.2@6317,3061 6321.47,3065.47 6321.47,3095.47 v1(6323,3097)
  Layer 8 w12: C212.2@3743.28,4197.58 v1(3773.27,4197.6) ; C206.2@4046.76,4199.95 4052.57,4205.76 4065.49,4205.76 4071.27,4211.55 v1(4072.35,4211.55) ; U44.2@4088.27,4097.6 4088.98,4098.31 4117.55,4098.31 v1(4118.27,4097.6) ; U34.15@5018.27,1947.6 5018.77,1947.1 U34.15@5019.57,1947.1 v1(5064.57,1947.1) ; U34.9@5018.27,2097.6 5018.77,2097.1 U34.9@5019.57,2097.1 v1(5064.57,2097.1) ; U43.2@5036.62,606.46 5036.94,606.79 5036.94,652.27 v1(5037.27,652.6) ; v1@5053.27,3107.6 5090.07,3107.6 U38.15@5091.57,3106.1 ; v1@5173.27,1377.6 5174.65,1378.98 5174.65,1398.6 5178.58,1398.6 5192.38,1412.39 5192.38,1422.2 5211.41,1441.23 U32.12@5211.41,1444.98 ; v1(5178.27,1552.6) 5178.27,1573.54 5175.72,1576.09 5189.52,1589.88 5189.52,1599.92 U33.12@5206.49,1616.89 ; v1(5208.27,2692.6) 5209.03,2691.83 5209.03,2676.83 R78.1@5213.27,2672.6 ; v1(5218.27,2857.6) 5218.89,2858.22 5218.89,2881.98 C137.2@5218.27,2882.6 ; v1(5233.27,2772.6) 5249.35,2772.6 5251.01,2774.26 5274.93,2774.26 U26.2@5278.27,2777.6 ; v1(5471.21,4074.98) U1.7@5471.21,4118 ; C63.1@5927,591 5928.03,592.03 5929.24,593.24 5956.11,593.24 5962.97,600.1 5989.02,600.1 v1(5989.97,601.05) ; C236.2@6305.85,3016.22 C236.2@6306.94,3015.13
  Layer 8 w20: C139.2@2753.27,4741.22 2753.27,4745.16 2799.9,4791.79 2837.46,4791.79 U29.4@2838.27,4792.6 ; U46.2@3803.31,4097.57 v1(3833.27,4097.6) ; v1(4808.27,2227.6) 4868.27,2227.6 ; 4870.73,2227.1 4930.11,2286.48 C143.2@4971.92,2286.48 ; v1(4887.13,2458.8) 4899.47,2458.8 4941.3,2500.63 4957.19,2500.63 4959,2502.44 C142.2@4959,2506.38 ; R141.2@4993.27,327.6 4997.77,323.09 v1(5022.62,323.09) ; R147.2@4993.27,467.6 4993.76,468.09 v1(5024.62,468.09) ; v1@5047,3257.6 5090.07,3257.6 U38.9@5091.57,3256.1 5093,3254.67 5141.85,3254.67 C171.1@5148.29,3248.22 5164.96,3248.22 5167.09,3250.35 5207.09,3250.35 5208.9,3252.16 R109.1@5208.9,3256.1 ; C205.2@5136.62,629.98 5139,627.6 5144,632.6 v1(5163.27,632.6) ; v5(5360.87,4302.79) v5(5360.87,4346.09) 5366.1,4340.86 R12.1@5402.2,4340.86 5402.2,4344.8 5408.66,4351.25 Q3.2@5460.96,4351.25 5464.9,4351.25 5491.71,4324.44 v1(5504.27,4324.44) ; U49.2@5493.27,3382.6 v1(5503.27,3382.6) 5523.11,3382.6 5524.92,3380.79 C242.1@5524.92,3379.22 5524.92,3376.9 5526.73,3375.09 5573.29,3375.09 R185.1@5577.42,3370.96 ; U50.2@5550.39,3542.6 v1(5558.27,3542.6) ; v1(5568.27,3717.6) 5611.26,3717.6 5615.39,3721.73 5615.39,3726.48 5595.39,3726.48 5593.58,3728.3 C209.2@5593.58,3732.23 ; R43.1@5874.65,327.79 5874.65,323.86 5876.46,322.05 5910.39,322.05 C78.1@5928.27,304.17 ; R38.1@5874.65,610.9 5909.16,610.9 C63.1@5928.03,592.03 ; C61.2@5918.27,460.57 5918.27,456.64 5920.08,454.83 5926.97,454.83 5931.79,450 5979.27,450 5979.82,450.55 5989.47,450.55 v1(5989.97,451.05) ; C255.2@8144.93,4121.83 8144.93,4125.76 8146.74,4127.58 C255.2@8154.88,4127.58 ; C255.2@8149.47,4117.43 C255.2@8152.63,4120.59 8152.63,4125.33 C255.2@8154.88,4127.58 ; C255.2@8159.88,4127.58 C255.2@8154.88,4127.58
  other v1: 7464,153 5905,163 7464,174 6318,223 6318,242 7306,271 6317.13,302.52 7249,306 6317.13,320.71 7527.27,327.29 7548.54,327.29 7443,344 7527.27,354.7 7548.54,354.7 7443,365 7527.27,382.11 7548.54,382.11 7527.27,409.52 7548.54,409.52 6273.32,412.03 6291.52,412.03 6309.71,412.03 7527.27,436.92 7548.54,436.92 7527.27,464.33 7548.54,464.33 7527.27,491.74 7548.54,491.74 6273.32,504.6 6291.52,504.6 6309.71,504.6 7527.27,519.15 7548.54,519.15 7527.27,546.56 7548.54,546.56 7527.27,573.97 7548.54,573.97 6273.32,592.97 6291.52,592.97 6309.71,592.97 7527.27,601.37 7548.54,601.37 7527.27,628.78 7548.54,628.78 7840.27,643.81 7942.59,643.81 8145,645 7527.27,656.19 7548.54,656.19 6257,664 7840.27,665.36 7942.59,665.36 7527.27,683.6 7548.54,683.6 6256.99,687.94 6275.19,687.94 7264.16,750.08 7264.16,771.71 6221.5,773.51 6221.5,796.27 3642.04,797.63 3670.04,797.63 6380.85,979.25 6482.85,984.25 6380.85,997.84 6483.17,1002.6 3576.27,1010.72 3577,1033 5174.65,1378.6 5140,1815 5437.27,2104.6 5457.27,2104.6 5477.27,2104.6 5497.27,2104.6 5517.27,2104.6 5918.27,2104.6 5938.27,2104.6 5958.27,2104.6 5978.27,2104.6 5998.27,2104.6 2062.27,2157.6 2062.65,2185.6 2062.65,2213.6 5438.27,2237.6 5458.27,2237.6 5478.27,2237.6 5498.27,2237.6 5518.27,2237.6 5918.27,2237.6 5938.27,2237.6 5958.27,2237.6 5978.27,2237.6 5998.27,2237.6 5478.27,2372.6 5498.27,2372.6 5518.27,2372.6 5918.27,2372.6 5938.27,2372.6 5958.27,2372.6 5978.27,2372.6 5998.27,2372.6 5458.27,2507.6 5478.27,2507.6 5498.27,2507.6 5518.27,2507.6 5918.27,2507.6 5938.27,2507.6 5958.27,2507.6 5978.27,2507.6 5998.27,2507.6 5975.27,2564.6 5995.27,2564.6 5414,2585 5975.27,2586.6 5995.27,2586.6 5347,2636 5427,2636 5386,2637 2083.27,2695.6 2083.65,2723.6 2083.65,2751.6 5047,3106.1 5047,3256.1 6204.02,3491.6 6478,3503 6204.02,3511.6 5903,3522 5903,3541 6159.27,3589.47 6179.27,3589.47 6199,3589.47 6217.27,3589.47 7459.27,3591.6 7559.27,3591.6 5568.27,3622.6 6159.27,3681.17 6179.27,3681.17 6199,3681.17 6217.27,3681.17 6159.27,3772.87 6179.27,3772.87 6199,3772.87 6217.27,3772.87 5368.27,3802.6 6159.27,3863.57 6179.27,3863.57 6199,3863.57 6217.27,3863.57 7830.73,3940.24 7930.73,3939.57 6159.27,3960.14 6179.27,3960.14 6199,3960.14 6217.27,3960.14 7830.73,3966.77 7930.73,3966.77 5833.27,3984.66 5853.26,3984.66 6199.02,4031.33 6199.02,4049.6 6317.27,4063.6 6317.27,4083.6 3412,4139 3512,4140 3612,4141 5373.37,4173.15 5395.44,4173.13 7917.02,4177.1 5373.37,4192.36 5395.44,4192.36 7917.27,4199.6 5373.37,4211.6 5395.44,4211.6 3264,4219 3245,4220 3244,4292 6053.05,4348.72 6075.55,4348.72 6098.05,4348.72 7107.27,4350.9 6053.05,4371.9 6075.55,4371.9 6098.05,4371.9 7263.86,4391.1 5153.27,4415.59 5175.77,4415.59 5198.27,4415.59 5153.27,4436.5 5175.77,4436.5 5198.27,4436.5 2588.27,4562.6 2613.27,4562.6 2593.27,5027.6 2613.27,5027.6
  other v5: 6202.75,2364.2 6180.11,2401.6 6225.39,2401.6 6202.75,2439 5969.45,4271.25 5969.45,4314.56
QRG: C232.1 Q10.1 R176.1 | length 95.1
  Layer 1 w25: C232.1@5386.3,2368.03 C232.1@5386.3,2369.18 ; C232.1@5386.99,2369.87 C232.1@5386.3,2369.18 ; Q10.1@5391.84,2417.06 5391.84,2376.13 5386.3,2370.59 C232.1@5386.3,2369.18 ; Q10.1@5399.03,2417.75 5399.03,2436.98 5411.4,2449.35 5411.4,2451.91 5412.09,2452.6 R176.1@5414.65,2452.6
RDRV_H_A: R31.2 R32.1 U11.50 | length 112.7
  Layer 1 w10: R31.2@7017,4002 7015,4000 7015,3982 7021.63,3975.37 7021.63,3963.81 7028.44,3957 R32.1@7032.38,3957 ; R31.2@7023,4003.81 v1(7023,4028)
  Layer 8 w10: v1(7023,4028) 7023.56,4027.44 7023.56,3997.44 U11.50@7025,3996
  Layer 8 w12: U11.50@7023.88,3996.96 U11.50@7024.12,3996.71
RDRV_H_B: R41.2 R42.1 U15.50 | length 151.8
  Layer 1 w12: R42.1@6693,279.62 6693,275.68 6698.81,269.87 6713.97,269.87 6721,262.84 6721,236.81 6726.81,231 R41.2@6728,231 ; v1@6723.38,202 6725.15,203.77 6725.15,229.77 R41.2@6726.38,231
  Layer 8 w12: U15.50@6723,234 U15.50@6723.67,233.3 ; v1(6724,201) 6723.84,201.16 6723.84,233.16 U15.50@6723.67,233.3 ; U15.50@6725.55,247.97 6723.67,246.09 U15.50@6723.67,233.3
RDRV_H_C: R51.2 R52.1 U19.50 | length 95.6
  Layer 1 w12: v1@10435,3246 10435.15,3246.15 R51.2@10435.15,3269.19 ; R52.1@10441.38,3315 10441.5,3314.88 10441.5,3274.5 R51.2@10442,3274
  Layer 8 w12: U19.50@10433,3276 U19.50@10433.63,3276.63 ; v1@10434.13,3247.87 10434.13,3277.89 U19.50@10434.27,3278.02
  other v1: 10434,3246
RDRV_H_D: R61.2 R62.1 U23.50 | length 144.8
  Layer 1 w10: R62.1@9858,1288 9859.62,1289.62 R61.2@9859.62,1329
  Layer 1 w20: R62.1@9859.65,1287.6 9859.65,1255.82 9869,1246.46 v3(9869,1246)
  Layer 8 w10: v3@9868,1247 9868,1244.84 9877.97,1234.87 9877.97,1198.73 U23.50@9880.84,1195.86 ; v3@9869,1247 v3@9869.84,1246.16
RDRV_H_PFC_1: R102.2 R103.1 U37.50 | length 191.4
  Layer 1 w10: R103.1@4404,1687.62 4404,1683.68 4425.56,1662.13 4443.19,1662.13 4448,1657.32 R102.2@4448,1651 ; R102.2@4450,1651.38 4450,1647.44 4473.5,1623.94 4473.5,1603.86 4494,1583.36 v1@4494,1583 ; v1@4488,1587.87 4488.49,1587.87 4492.15,1584.21 v1@4492.15,1583.72
  Layer 8 w10: U37.50@4460,1584 4460.87,1584.87 U37.50@4463.12,1584.87 v1(4493.12,1584.87)
RDRV_H_PFC_2: R112.2 R113.1 U41.50 | length 199.3
  Layer 1 w10: R113.1@4337.63,2660.22 4425.19,2660.22 4432.84,2667.87 4465.16,2667.87 4474.28,2658.75 4494.25,2658.75 v1@4496,2657
  Layer 8 w10: U41.50@4463.12,2656.2 4463.82,2656.9 4495.9,2656.9 v1@4496,2657
  other v1: 4504,2657
RDRV_L_A: R26.2 R27.1 U9.50 | length 58.8
  Layer 1 w10: v1(6509,4027) 6509,4009 R26.2@6514,4004 ; R27.1@6523.73,4004 R27.1@6526.3,4004
  Layer 8 w10: U9.50@6509,3996 6509.24,3996.24 6509.24,4026.76 v1(6509,4027)
RDRV_L_B: R36.2 R37.1 U13.50 | length 106.8
  Layer 1 w12: R36.2@7239,225 7240.5,226.5 7240.5,268.12 R37.1@7239.62,269 ; R36.2@7242,232 7242.19,231.81 7242.19,203.81 v1(7243,203)
  Layer 8 w12: v1(7243,203) 7243.34,203.34 7243.34,234.34 U13.50@7244,235
RDRV_L_C: R46.2 R47.1 U17.50 | length 159.7
  Layer 1 w10: v1(9930,3247) 9931.53,3245.47 9931.53,3207.47 R46.2@9936,3203 ; R46.2@9936.45,3201.87 9936.45,3198.64 9943.26,3191.83 9955.18,3191.83 9978.9,3168.11 9978.9,3163.41 9985.71,3156.6 R47.1@9989.65,3156.6
  Layer 1 w12: R46.2@9930,3203.62 R46.2@9932.02,3201.6
  Layer 8 w10: v1(9930,3247) 9929.63,3247.37 9929.63,3278.63 U17.50@9931,3280
RDRV_L_D: R56.2 R57.1 U21.50 | length 144.1
  Layer 1 w12: R57.1@10380,1276 10378,1274 10378,1257 10390.54,1244.46 10390.54,1234.01 v3@10391.69,1232.86 ; v3(10389,1233) 10390.15,1231.85 10390.15,1218.05 10393.08,1215.12 10393.08,1206.36 10408.44,1191 R56.2@10413,1191
  Layer 1 w20: R57.1@10382.89,1276.6 10383.19,1276.6 R57.1@10385,1278.41
  Layer 8 w10: U21.50@10391.69,1195.86 v3@10391.69,1232.86
RDRV_L_PFC_1: R97.2 R98.1 U35.50 | length 192.8
  Layer 1 w10: R97.2@4467,2119 R97.2@4473.93,2112.07 ; R97.2@4475.54,2118.88 R97.2@4471.6,2118.88 4478.41,2112.07 4489.23,2112.07 4508.3,2093 v1@4511,2093 ; v1@4507.22,2094.44 v1@4508.37,2093.29 ; v1@4509.42,2093.29 v1(4510,2093.29)
  Layer 8 w10: U35.50@4463.12,2093.29 v1(4510,2093.29) 4511.53,2094.82 4517.82,2094.82 4531.83,2108.83 4549.51,2108.83 4570.71,2130.02 R98.1@4574.65,2130.02
RDRV_L_PFC_2: R107.2 R108.1 U39.50 | length 216.9
  Layer 1 w20: R108.1@4341.27,3066.98 4342.65,3065.6 4377.89,3065.6 4375.89,3067.6 v1(4360.27,3067.6)
  Layer 8 w10: v1(4360.27,3067.6) 4360.27,3097.39 4428.66,3165.78 U39.50@4460.45,3165.78 ; U39.50@4460.27,3165.6 U39.50@4460.45,3165.78 ; U39.50@4463.12,3165.78 U39.50@4460.45,3165.78
Re_C_1: D9.1 K1.2 Q5.2 Q5.4 | length 603.3
  Layer 1 w50: K1.2@3313.67,857.75 3327.98,857.75 3419.1,766.63 D9.1@3476.14,766.63
  Layer 8 w50: K1.2@3313.67,857.75 3357.75,857.75 Q5.4@3436.34,936.34 ; Q5.4@3432.09,936.34 Q5.4@3436.34,936.34 ; Q5.2@3680,936.34 Q5.4@3436.34,936.34
Re_C_2: D8.1 K1.1 R157.1 R158.1 | length 331.2
  Layer 1 w50: K1.1@3313.67,1054.6 3454.49,1054.6 3460.76,1048.33 ; R157.1@3460.17,1207.83 R158.1@3460.17,1117.83 3460.76,1117.24 3460.76,1048.33 ; D8.1@3476.14,1032.94 3460.76,1048.33
ROG_PRI_N: R67.1 T2.2 | length 259.3
  Layer 1 w12: R67.1@6346.6,3283.25 6346.6,3279.31 6462.92,3163 6552.36,3163 T2.2@6553.36,3164
ROG_PRI_P: R69.1 T2.1 | length 336
  Layer 1 w12: R69.1@6298,3245 6298,3241.44 6303.81,3235.63 6307.37,3235.63 6497.65,3045.35 6502,3045.35 T2.1@6535.36,3012
ROG_SEC_N: J1.2 R179.1 | length 65.9
  Layer 8 w12: J1.2@6215.31,2946 J1.2@6217.97,2946 6229.11,2946 6254.29,2920.81 6261.19,2920.81 R179.1@6268,2914
ROG_SEC_P: J1.1 R181.1 | length 96.6
  Layer 8 w12: J1.1@6120.52,2964.71 J1.1@6139.23,2946 ; J1.1@6139,2947 6139.38,2947.38 R181.1@6139.38,3017
SGND: C1.1 C18.1 C19.2 C20.1 C21.2 C82.1 C84.2 C86.1 C87.2 C88.2 C89.2 C90.2 C91.1 C92.1 C93.2 C94.2 C95.1 C96.1 C104.1 C106.2 C108.1 C109.2 C110.2 C111.2 C112.2 C113.1 C114.1 C115.2 C116.2 C117.1 C118.1 C255.1 J21.4 J23.4 J36.2 J36.4 L7.1 L9.1 R1.1 R2.1 R3.1 R4.1 R5.1 R46.1 R56.1 R192.2 R205.1 TP1.1 U16.2 U16.8 U17.17 U17.18 U17.19 U17.20 U17.21 U17.22 U17.23 U17.24 U17.25 U17.26 U17.27 U17.28 U17.29 U17.30 U17.31 U17.32 U17.33 U17.34 U17.35 U17.36 U17.37 U17.38 U17.39 U20.2 U20.8 U21.17 U21.18 U21.19 U21.20 U21.21 U21.22 U21.23 U21.24 U21.25 U21.26 U21.27 U21.28 U21.29 U21.30 U21.31 U21.32 U21.33 U21.34 U21.35 U21.36 U21.37 U21.38 U21.39 | length 7656.6
  Layer 1 w10: J36.2@8625,4132 v1(8655,4132) ; J36.4@8718,4131 8719,4132 v1(8752,4132) ; v1(9258.27,4167.6) 9493.27,4167.6 9683.27,4357.6 10018.27,4357.6 10083.27,4292.6 10083.27,4032.6 10098.27,4017.6 10168.27,4017.6 ; v1@9990,3232 10004.55,3232 10032.95,3203.6 C87.2@10036.89,3203.6
  Layer 1 w12: U16.2@8379,3791 8379.25,3791.25 8422.75,3791.25 v1(8423,3791) ; U16.8@8382.3,3941.5 8384.37,3943.57 8422.95,3943.57 8424.38,3945 v1(8426,3945) ; U20.2@8397,58 8397.75,58.75 8440.75,58.75 v1(8441,59) ; U20.8@8398,209 8399.44,207.56 C106.2@8459.06,207.56 ; C106.2@8467,206 8469.31,208.31 8489.31,208.31 v1(8490,209)
  Layer 1 w20: v3(10314.51,1195.86) 10322.64,1187.72 10337.46,1187.72 10339.27,1185.91 C109.2@10339.27,1181.98
  Layer 1 w25: 10572.02,1162.06 10627.61,1162.06 C104.1@10640.11,1174.56
  Layer 1 w100: C20.1@10238.27,3838.57 10519.48,3557.35 TP1.1@10871.53,3557.35
  Layer 7 w10: v1(8655,4132) 8930.6,4407.6 10323.27,4407.6 10481.85,4249.01 v1(10481.85,3908.46) 10453.27,3937.04 10453.27,4237.6 10303.27,4387.6 9006.6,4387.6 v1@8751,4132
  Layer 8 w10: v1@9258.27,4162.6 9263.27,4167.6 R192.2@9301.18,4167.6 ; R192.2@9303.27,4167.6 R205.1@9303.27,4243.98
  Layer 8 w12: v3@10573,1131 v3@10573,1134.62
  Layer 8 w100: C21.2@10191.28,350.6 10191.28,590.61 C18.1@10200.27,599.6 ; C19.2@10226.83,4073.81 10226.83,3850.01 C20.1@10238.27,3838.57
  other v1: 10101.27,200.29 10122.54,200.29 10101.27,227.7 10122.54,227.7 10101.27,255.11 10122.54,255.11 10101.27,282.52 10122.54,282.52 10101.27,309.92 10122.54,309.92 10101.27,337.33 10122.54,337.33 10101.27,364.74 10122.54,364.74 10101.27,392.15 10122.54,392.15 10101.27,419.56 10122.54,419.56 8745.27,431.6 10101.27,446.97 10122.54,446.97 8745,452 10101.27,474.37 10122.54,474.37 10101.27,501.78 10122.54,501.78 10101.27,529.19 10122.54,529.19 10101.27,556.6 10122.54,556.6 9394.32,1235.95 9415.6,1235.95 9394.32,1263.36 9415.6,1263.36 9394.32,1290.77 9415.6,1290.77 10584.99,1303.88 10606.27,1303.88 9394.32,1318.18 9415.6,1318.18 10584.99,1330.51 10606.27,1330.51 9394.32,1345.58 9415.6,1345.58 10584.99,1357.14 10606.27,1357.14 9394.32,1372.99 9415.6,1372.99 10584.99,1383.76 10606.27,1383.76 9394.32,1400.4 9415.6,1400.4 10584.99,1410.39 10606.27,1410.39 9394.32,1427.81 9415.6,1427.81 10584.99,1437.02 10606.27,1437.02 9394.32,1455.22 9415.6,1455.22 10584.99,1463.65 10606.27,1463.65 9394.32,1482.62 9415.6,1482.62 10584.99,1490.27 10606.27,1490.27 9394.32,1510.03 9415.6,1510.03 10584.99,1516.9 10606.27,1516.9 9394.32,1537.44 9415.6,1537.44 10584.99,1543.53 10606.27,1543.53 9394.32,1564.85 9415.6,1564.85 10584.99,1570.15 10606.27,1570.15 9394.32,1592.26 9415.6,1592.26 10584.99,1596.78 10606.27,1596.78 9394.32,1619.67 9415.6,1619.67 10606.27,1624.19 10606.27,1651.6 9590.16,3031.25 9565,3032 9723,3135 9723,3157 9850.69,3174.56 9851,3199 9564,3208 9593,3210 9990,3231 9578.02,3398.99 9620.27,3398.99 9544.77,3399.99 9620.27,3432.18 9544.77,3433.18 9620.27,3465.38 9546,3499 9620.27,3498.58 9620.27,3531.77 9563.93,3564.08 9592.1,3564.08 9620.27,3564.97 9544.77,3565.97 9620.27,3598.17 9544.77,3599.17 9620.27,3631.36 9547,3654 9620.27,3664.56 8655,3689 8655,3710 10320.99,3895.29 10342.27,3895.29 10320.99,3922.7 10342.27,3922.7 10320.99,3950.11 10342.27,3950.11 10320.99,3977.52 10342.27,3977.52 10320.99,4004.92 10342.27,4004.92 10320.99,4032.33 10342.27,4032.33 10320.99,4059.74 10342.27,4059.74 10320.99,4087.15 10342.27,4087.15 10320.99,4114.56 10342.27,4114.56 10320.99,4141.97 10342.27,4141.97 10320.99,4169.37 10342.27,4169.37 10320.99,4196.78 10342.27,4196.78 10320.99,4224.19 10342.27,4224.19 10320.99,4251.6 10342.27,4251.6
  other v2: 8487,3739 8487,3754
  other v3: 10551,1132 10572,1132 10457.46,1232.86 10477.46,1232.86 10457.24,1252.37 10477.24,1252.37
SW_A: C10.2 C12.2 C14.2 C16.2 C53.1 C55.2 C57.1 C58.2 C59.2 J17.1 L4.1 R31.1 U9.1 U9.2 U9.3 U9.4 U9.5 U9.6 U9.7 U9.8 U9.9 U9.10 U9.11 U9.12 U9.13 U9.14 U9.15 U9.16 U10.2 U10.8 U11.17 U11.18 U11.19 U11.20 U11.21 U11.22 U11.23 U11.24 U11.25 U11.26 U11.27 U11.28 U11.29 U11.30 U11.31 U11.32 U11.33 U11.34 U11.35 U11.36 U11.37 U11.38 U11.39 | length 116.7
  Layer 1 w12: v1@6947.27,4028 6946.94,4027.68 6946.94,4009.84 6947.87,4008.91 6947.87,4002.81 6953.68,3997 R31.1@6959.38,3997 ; U10.2@7106.69,4098.3 7108.76,4096.23 7108.76,4059.86 7109,4059.62 v1@7109,4057 ; v1(7110,4057) 7111.15,4055.85 7111.15,4048.54 7124.69,4035 C55.2@7128.62,4035 C55.2@7130,4035
  Layer 8 w12: v1@6902.27,3913.6 v1(6902.27,3915)
  other v1: 6867.27,3466.94 6891.68,3466.94 6916.09,3466.94 6940.5,3466.94 6964.91,3466.94 6989.32,3466.94 7013.73,3466.94 7038.15,3466.94 7062.56,3466.94 7086.97,3466.94 7111.38,3466.94 7135.79,3466.94 6867.27,3489.94 6891.68,3489.94 6916.09,3489.94 6940.5,3489.94 6964.91,3489.94 6989.32,3489.94 7013.73,3489.94 7038.15,3489.94 7062.56,3489.94 7086.97,3489.94 7111.38,3489.94 7135.79,3489.94 6923,3915 7081,3916 6948,4032 7276,4062 6763.27,4080.6 6789.27,4080.6
SW_A_RES: C10.1 C12.1 C14.1 C16.1
  other v1: 6887.27,3247.5 6911.68,3247.5 6936.09,3247.5 6960.5,3247.5 6984.91,3247.5 7009.32,3247.5 7033.73,3247.5 7058.15,3247.5 7082.56,3247.5 7106.97,3247.5 7131.38,3247.5 7155.79,3247.5 6887.27,3270.5 6911.68,3270.5 6936.09,3270.5 6960.5,3270.5 6984.91,3270.5 7009.32,3270.5 7033.73,3270.5 7058.15,3270.5 7082.56,3270.5 7106.97,3270.5 7131.38,3270.5 7155.79,3270.5
  other v6: 6795.36,3307.5
SW_A_XFMR: L19.2 T1.2
  other v6: 6885.05,2867.57
SW_B: C2.2 C4.2 C6.2 C8.2 C75.1 C77.2 C79.1 C80.2 C81.2 J19.1 L6.1 R41.1 U13.1 U13.2 U13.3 U13.4 U13.5 U13.6 U13.7 U13.8 U13.9 U13.10 U13.11 U13.12 U13.13 U13.14 U13.15 U13.16 U14.2 U14.8 U15.17 U15.18 U15.19 U15.20 U15.21 U15.22 U15.23 U15.24 U15.25 U15.26 U15.27 U15.28 U15.29 U15.30 U15.31 U15.32 U15.33 U15.34 U15.35 U15.36 U15.37 U15.38 U15.39 | length 2170.3
  Layer 1 w12: U14.2@6163.26,161.36 U14.2@6162.57,162.05 U14.2@6163.82,162.05 ; U14.2@6163.27,162.6 U14.2@6163.82,162.05 ; 6202.57,157.37 6214.57,157.37 6220.38,151.55 C77.2@6220.38,147.62 ; 6202.57,162.05 U14.2@6163.82,162.05
  Layer 7 w25: 6571,159 6568.55,161.45 6202.55,161.45 6159,205 6159,419.03 6179,439.03 6179,811 6233,865 7084.46,865 7162.73,943.27 v1(7162.73,963.81)
  other v1: 7043.4,125.43 7062.52,125.43 6935.43,143.48 6935.43,162.6 6758,273 6659,277 6709.48,321.78 6729.48,321.78 7163,943
SW_B_RES: C2.1 C4.1 C6.1 C8.1 C256.2 Q1.2 T1.1 | length 384.1
  Layer 1 w25: T1.1@6993,1681 6993,1628.73 T1.1@7010,1611.73
  Layer 1 w50: T1.1@7010,1633 7010,1611.73 7010,1605.57 7011.08,1604.49 7020.79,1604.49 7138,1487.28 C256.2@7138,1383.93
SW_C: C11.2 C13.2 C15.2 C17.2 C97.1 C99.2 C101.1 C102.2 C103.2 J21.1 L8.1 R51.1 U17.1 U17.2 U17.3 U17.4 U17.5 U17.6 U17.7 U17.8 U17.9 U17.10 U17.11 U17.12 U17.13 U17.14 U17.15 U17.16 U18.2 U18.8 U19.17 U19.18 U19.19 U19.20 U19.21 U19.22 U19.23 U19.24 U19.25 U19.26 U19.27 U19.28 U19.29 U19.30 U19.31 U19.32 U19.33 U19.34 U19.35 U19.36 U19.37 U19.38 U19.39 | length 147.9
  Layer 1 w10: U18.2@8380,4217 8384.17,4212.83 8428.8,4212.83 8429.25,4212.37 8433.19,4212.37 8440,4205.56 C99.2@8440,4203 ; U18.8@8382,4365 8385.57,4368.57 8424.41,4368.57 8427.84,4372 v1(8430,4372) ; C99.2@8440,4201.62 C99.2@8440,4203 ; v1(8464,4204) 8441,4204 C99.2@8440,4203
  Layer 1 w12: C101.1@10371.68,3275 C101.1@10375.62,3275
  other v1: 10035.55,2684.38 10059.96,2684.38 10084.37,2684.38 10108.78,2684.38 10133.19,2684.38 10157.6,2684.38 10182.01,2684.38 10206.42,2684.38 10230.84,2684.38 10255.25,2684.38 10279.66,2684.38 10035.55,2707.38 10059.96,2707.38 10084.37,2707.38 10108.78,2707.38 10133.19,2707.38 10157.6,2707.38 10182.01,2707.38 10206.42,2707.38 10230.84,2707.38 10255.25,2707.38 10279.66,2707.38 10221,3123 10221,3145 10474.52,3174.48 10474,3197 10495,3214 10359,3239 10486,3240 8631.27,3961.68 8631.27,3984.6
SW_C_RES: C11.1 C13.1 C15.1 C17.1
  other v1: 10035.55,2473.45 10059.96,2473.45 10084.37,2473.45 10108.78,2473.45 10133.19,2473.45 10157.6,2473.45 10182.01,2473.45 10206.42,2473.45 10230.84,2473.45 10255.25,2473.45 10279.66,2473.45 10304.07,2473.45 10059.96,2496.45 10084.37,2496.45 10108.78,2496.45 10133.19,2496.45 10157.6,2496.45 10182.01,2496.45 10206.42,2496.45 10230.84,2496.45 10255.25,2496.45 10279.66,2496.45 10304.07,2496.45
  other v6: 9976,2529
SW_C_XFMR: T1.3
  other v6: 9621.78,2529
